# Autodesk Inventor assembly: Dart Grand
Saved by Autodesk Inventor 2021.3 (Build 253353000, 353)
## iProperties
Created: 2022-09
Part Number: Dart Grand
Document SubType Name: Assembly
Designer: Administrator
Title: Dart Grand v7
Author: Administrator
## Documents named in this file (3)
- c:\worker\convert-fusion-r05\tmp\job-1\4358\output\files\52827ae5-e37f-44c4-a7b5-27d499f46ec8\c52231b9-2b2c-48b2-b03f-86f60d7406a1.iam
- c:\worker\convert-fusion-r05\tmp\job-1\4358\output\files\52827ae5-e37f-44c4-a7b5-27d499f46ec8\Dart Grand.ipt
- c:\worker\convert-fusion-r05\tmp\job-1\4358\output\files\52827ae5-e37f-44c4-a7b5-27d499f46ec8\Part4.ipt
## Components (2 placed, 2 different names)
1. Dart Grand:1
2. Part4
